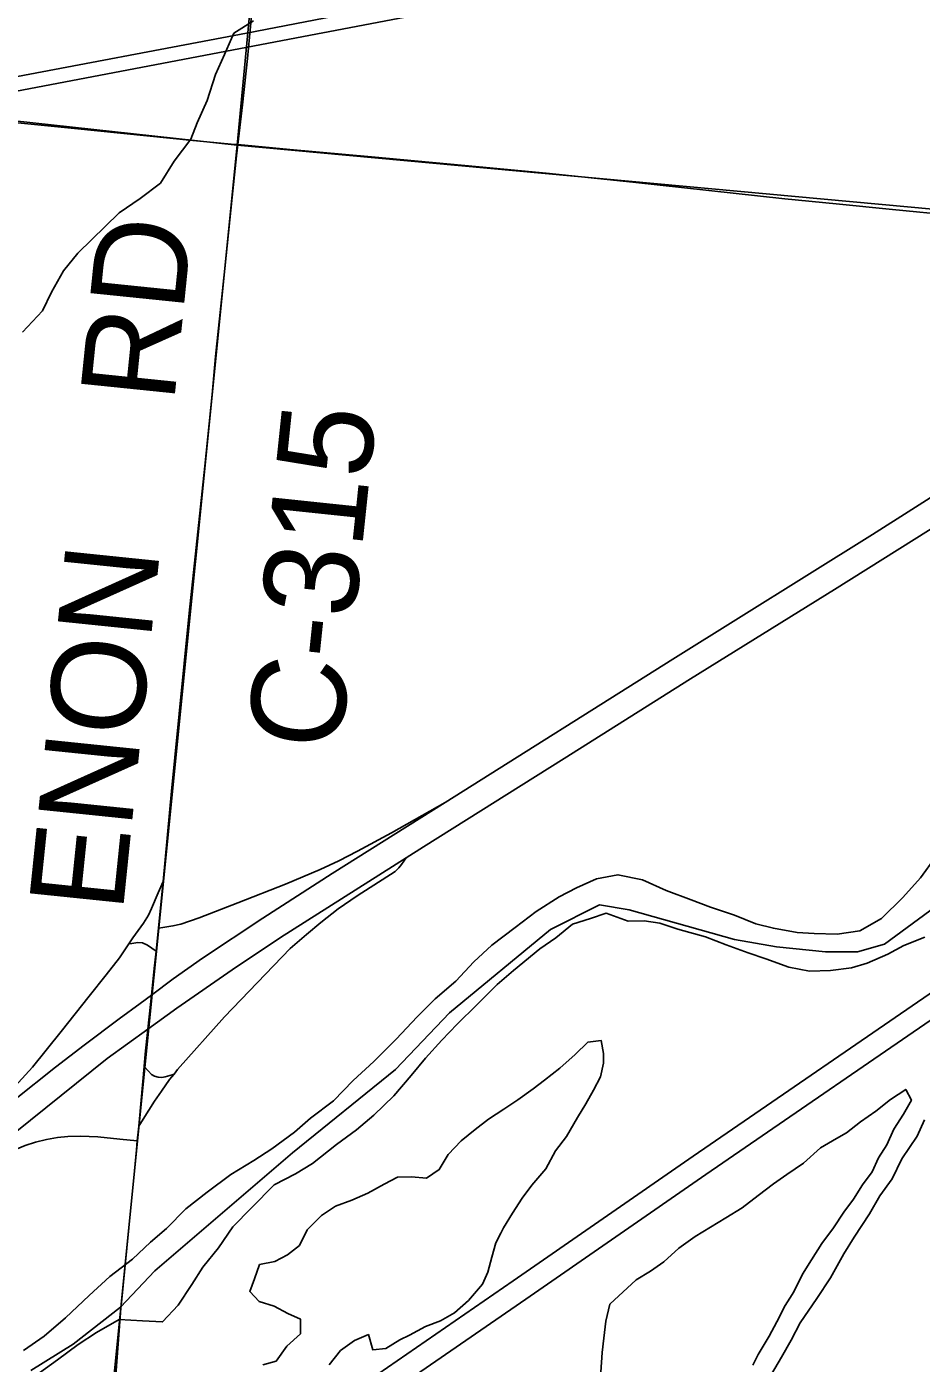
# Model space of a CAD drawing. Extents: x 0 to 34, y 0 to 22.
# Drawn here: x 2.851 to 3.39, y 15.759 to 16.564 of the extents above; entities that cross this region are included whole.
import ezdxf

# ---------------------------------------------------------------- set-up
doc = ezdxf.new("R2010")
doc.units = 0
for name, color, linetype in [('Default', 7, 'Continuous'), ('GM_X_City_Street', 7, 'Continuous'), ('GM_X_County_Road', 7, 'Continuous'), ('GM_X_County_Road_Text', 7, 'Continuous'), ('GM_X_Interchange_Ramps', 7, 'Continuous'), ('GM_X_Major_River', 7, 'Continuous'), ('GM_X_Minor_Lake', 7, 'Continuous'), ('GM_X_Minor_River', 7, 'Continuous'), ('GM_X_Rail_Line', 7, 'Continuous'), ('GM_X_Section', 7, 'Continuous'), ('GM_X_State_Route', 7, 'Continuous')]:
    doc.layers.add(name, color=color, linetype=linetype)

msp = doc.modelspace()

# ---------------------------------------------------------------- linework, layer by layer
at = {"layer": 'Default'}
for points in [[(2.1, 17.59573), (2.1, 16.58828), (2.97812, 16.49217), (3.07459, 17.51121)], [(2.1, 16.58828), (2.1, 15.58132), (2.87773, 15.48948), (2.97812, 16.49217)]]:
    msp.add_lwpolyline(points, close=True, dxfattribs=at)
at = {"layer": 'GM_X_City_Street'}
for points in [[(3.4019, 16.03619), (3.36789, 16.01106), (3.3516, 16.00661), (3.33238, 16.00662), (3.30277, 16.0096), (3.27745, 16.01401), (3.21402, 16.0318), (3.19625, 16.03478), (3.16667, 16.02001), (3.10601, 15.96974), (3.07345, 15.93573), (3.01133, 15.88546), (2.92847, 15.8145), (2.90781, 15.79254), (2.87924, 15.77038), (2.85389, 15.7544)], [(2.85389, 15.7544), (2.87924, 15.77038), (2.90781, 15.79254), (2.92847, 15.8145), (3.01133, 15.88546), (3.07345, 15.93573), (3.10601, 15.96974), (3.16667, 16.02001), (3.19625, 16.03478), (3.21402, 16.0318), (3.27745, 16.01401), (3.30277, 16.0096), (3.33238, 16.00662), (3.3516, 16.00661), (3.36789, 16.01106), (3.4019, 16.03619)]]:
    msp.add_lwpolyline(points, dxfattribs=at)
at = {"layer": 'GM_X_County_Road'}
msp.add_line((2.91792, 15.89272), (2.91874, 15.90146), dxfattribs=at)
for points in [[(2.97837, 16.49255), (2.98124, 16.51654), (2.98428, 16.54434), (2.986, 16.56374), (2.98874, 16.59379), (2.99255, 16.63087), (2.99634, 16.66794), (2.99894, 16.69376), (3.00125, 16.7176), (3.00368, 16.7471), (3.00661, 16.77881), (3.00876, 16.80356), (3.01273, 16.84371), (3.02155, 16.93329), (3.03145, 17.03525), (3.04182, 17.14033), (3.04653, 17.18666), (3.0502, 17.22374), (3.05249, 17.24848), (3.05784, 17.30412), (3.06286, 17.35669), (3.06386, 17.36665)], [(2.1, 16.53048), (2.1009, 16.5306), (2.1287, 16.53392), (2.18123, 16.53969), (2.26467, 16.54874), (2.31107, 16.55357), (2.3266, 16.5548), (2.33595, 16.55516), (2.34533, 16.55503), (2.35778, 16.55419), (2.41922, 16.54792), (2.47798, 16.54185), (2.52745, 16.53676), (2.6698, 16.52317), (2.7348, 16.51697), (2.7657, 16.51363), (2.80591, 16.50961), (2.88015, 16.50226), (2.95129, 16.4951), (2.9767, 16.4927), (2.97837, 16.49255)], [(2.94316, 16.14982), (2.94923, 16.21034), (2.95855, 16.29886), (2.96298, 16.34216), (2.96509, 16.36491), (2.96671, 16.38197), (2.97065, 16.41795), (2.97495, 16.46098), (2.97755, 16.48571), (2.97837, 16.49255)], [(2.97837, 16.49255), (3.00975, 16.48956), (3.05897, 16.48522), (3.12374, 16.47912), (3.16403, 16.47542), (3.21637, 16.47004), (3.30781, 16.45986), (3.33874, 16.4569), (3.37274, 16.45355), (3.40986, 16.44998)], [(2.93344, 16.04896), (2.93841, 16.10325), (2.94256, 16.14387), (2.94316, 16.14982)], [(2.92922, 16.00702), (2.93067, 16.02084), (2.93215, 16.03496), (2.93344, 16.04896)], [(2.92202, 15.93755), (2.92266, 15.94484), (2.92425, 15.95988), (2.92642, 15.9804), (2.92811, 15.99646), (2.92922, 16.00702)], [(2.91874, 15.90146), (2.92023, 15.91716), (2.92202, 15.93755)], [(2.91617, 15.87463), (2.91741, 15.88735), (2.91792, 15.89272)], [(2.89704, 15.66935), (2.89755, 15.67486), (2.89763, 15.6757), (2.90075, 15.70615), (2.90467, 15.74642), (2.9075, 15.78663), (2.90804, 15.79201), (2.90817, 15.79337), (2.91286, 15.84038), (2.91617, 15.87463)]]:
    msp.add_lwpolyline(points, dxfattribs=at)
at = {"layer": 'GM_X_Interchange_Ramps'}
for points in [[(3.10321, 16.09644), (3.07101, 16.07812), (3.05044, 16.06714), (3.03932, 16.06132), (3.02794, 16.05605), (3.00714, 16.04731), (2.97852, 16.036), (2.95512, 16.02696), (2.94403, 16.02321), (2.93935, 16.02214), (2.93333, 16.02124), (2.93067, 16.02084)], [(2.91874, 15.90146), (2.92145, 15.90572), (2.92834, 15.91655), (2.93252, 15.92268), (2.93735, 15.92956), (2.94002, 15.93292), (2.94222, 15.93569), (2.97043, 15.96737), (3.01004, 16.00849), (3.01973, 16.01699), (3.02853, 16.02413), (3.03879, 16.03244), (3.05038, 16.04027), (3.07328, 16.05498), (3.07543, 16.05717), (3.07696, 16.05913), (3.07979, 16.06315)], [(2.93344, 16.04896), (2.93049, 16.04199), (2.92653, 16.03263), (2.92459, 16.02861), (2.92164, 16.02379), (2.91524, 16.01502), (2.91279, 16.01132), (2.90718, 16.00286), (2.89919, 15.99274), (2.88888, 15.97986), (2.8721, 15.95854), (2.85476, 15.93703), (2.84644, 15.92785), (2.83565, 15.91674), (2.82413, 15.9054), (2.79041, 15.87142)], [(2.92922, 16.00702), (2.92675, 16.00876), (2.92409, 16.01063), (2.921, 16.01188), (2.91826, 16.01207), (2.9146, 16.01156), (2.91279, 16.01132)], [(2.92202, 15.93755), (2.92465, 15.93476), (2.92652, 15.93276), (2.92834, 15.93162), (2.93052, 15.93107), (2.93259, 15.93087), (2.93466, 15.93119), (2.93891, 15.93256), (2.94002, 15.93292)], [(2.80194, 15.86078), (2.82531, 15.87675), (2.83515, 15.88277), (2.84325, 15.88694), (2.85031, 15.88983), (2.85656, 15.89191), (2.86327, 15.89353), (2.86987, 15.89469), (2.876, 15.89538), (2.88375, 15.89562), (2.89417, 15.89504), (2.90736, 15.89376), (2.91792, 15.89272)]]:
    msp.add_lwpolyline(points, dxfattribs=at)
at = {"layer": 'GM_X_Major_River'}
for points in [[(3.39849, 16.06348), (3.38947, 16.05113), (3.37893, 16.03919), (3.36609, 16.02654), (3.353, 16.01923), (3.33926, 16.01725), (3.32557, 16.01756), (3.31532, 16.01817), (3.30092, 16.02077), (3.29033, 16.02329), (3.27752, 16.02852), (3.26317, 16.0334), (3.25148, 16.03785), (3.2364, 16.04351), (3.22209, 16.04991), (3.20733, 16.05291), (3.19434, 16.05053), (3.18243, 16.0451), (3.17204, 16.03962), (3.15814, 16.03081), (3.14538, 16.0212), (3.13144, 16.01049), (3.12057, 16.00046), (3.10966, 15.98892), (3.09724, 15.97816), (3.08635, 15.96738), (3.07388, 15.95397), (3.06026, 15.94058), (3.04784, 15.92907), (3.03615, 15.91678), (3.02222, 15.90645), (3.01252, 15.89792), (2.99898, 15.88795), (2.98818, 15.88097), (2.97429, 15.87253), (2.95998, 15.86182), (2.9472, 15.85184), (2.93552, 15.83994), (2.92583, 15.83179), (2.91495, 15.82138), (2.9014, 15.81104), (2.88897, 15.79953), (2.8746, 15.78616), (2.8618, 15.77504), (2.84943, 15.76657)], [(3.39208, 16.01532), (3.37942, 16.01027), (3.36979, 16.00516), (3.3575, 15.99973), (3.34793, 15.9969), (3.33534, 15.99528), (3.32278, 15.9948), (3.31029, 15.99736), (3.29632, 16.00224), (3.28576, 16.00589), (3.27255, 16.01075), (3.26011, 16.0156), (3.24348, 16.02015), (3.23253, 16.02382), (3.22305, 16.02517), (3.21354, 16.025), (3.20034, 16.02986), (3.19076, 16.02665), (3.18003, 16.02309), (3.16996, 16.01495), (3.1603, 16.00832), (3.14441, 15.99536), (3.13471, 15.98683), (3.12227, 15.97456), (3.1106, 15.96303), (3.10125, 15.95335), (3.0915, 15.94254), (3.08289, 15.93209), (3.07235, 15.91977), (3.0603, 15.90825), (3.04983, 15.89936), (3.03784, 15.8905), (3.02351, 15.87903), (3.01309, 15.8728), (3.0004, 15.86624), (2.98677, 15.85247), (2.97548, 15.84094), (2.96683, 15.8282), (2.95744, 15.81662), (2.95074, 15.80613), (2.94247, 15.79376), (2.93312, 15.7837), (2.92096, 15.78436)], [(2.92096, 15.78436), (2.9069, 15.78505), (2.89342, 15.77737), (2.88222, 15.77002), (2.86984, 15.76079), (2.85902, 15.75304)]]:
    msp.add_lwpolyline(points, dxfattribs=at)
at = {"layer": 'GM_X_Minor_Lake'}
for points in [[(3.13674, 15.83708), (3.13845, 15.8404), (3.14388, 15.84907), (3.14969, 15.85811), (3.15548, 15.86601), (3.16396, 15.87578), (3.16979, 15.88672), (3.17636, 15.89537), (3.18296, 15.90668), (3.188, 15.91497), (3.19266, 15.92327), (3.19693, 15.93119), (3.19856, 15.93952), (3.19862, 15.94522), (3.1972, 15.95321), (3.18922, 15.95217), (3.18152, 15.94467), (3.17231, 15.93643), (3.1631, 15.92932), (3.1562, 15.92409), (3.147, 15.91737), (3.13857, 15.91178), (3.12938, 15.90582), (3.12133, 15.89946), (3.11289, 15.89273), (3.10519, 15.88447), (3.09976, 15.87543), (3.09209, 15.87021), (3.08299, 15.87108), (3.07463, 15.8708), (3.0666, 15.86672), (3.05666, 15.86115), (3.04711, 15.85709), (3.03719, 15.85342), (3.02876, 15.84782), (3.0203, 15.83919), (3.01562, 15.82976), (3.00834, 15.82415), (3.00069, 15.82007), (2.99155, 15.81829)], [(3.31219, 15.80012), (3.31349, 15.80219), (3.31855, 15.81238), (3.32397, 15.82105), (3.33017, 15.83084), (3.33712, 15.84025), (3.34332, 15.84967), (3.34911, 15.85757), (3.35454, 15.86624), (3.36034, 15.87414), (3.36423, 15.88245), (3.36927, 15.89036), (3.37357, 15.8998), (3.37937, 15.90884), (3.38404, 15.91714), (3.3807, 15.92364), (3.37151, 15.91767), (3.36268, 15.91057), (3.35349, 15.90422), (3.34505, 15.89749), (3.33893, 15.89415), (3.32936, 15.88857), (3.31899, 15.8792), (3.30903, 15.87249), (3.30098, 15.86689), (3.29178, 15.85979), (3.28219, 15.85231), (3.27224, 15.84636), (3.25387, 15.83519), (3.24391, 15.8281), (3.23507, 15.81985), (3.22702, 15.81425), (3.21822, 15.80905), (3.20247, 15.79443)], [(3.03335, 15.75778), (3.04029, 15.76643), (3.04873, 15.7724), (3.05713, 15.77609), (3.05967, 15.76695), (3.06766, 15.76761), (3.07608, 15.77282), (3.08181, 15.77579), (3.09138, 15.78099), (3.10054, 15.78429), (3.10895, 15.78912), (3.1174, 15.79661), (3.12588, 15.80638), (3.12901, 15.81356), (3.1314, 15.82264), (3.13378, 15.83134), (3.13674, 15.83708)], [(2.99155, 15.81829), (2.9884, 15.80959), (2.98565, 15.80203), (2.99127, 15.79589), (3.00035, 15.79312), (3.00866, 15.78884), (3.01621, 15.78533), (3.01611, 15.7766), (3.00804, 15.76911), (3.00147, 15.76007), (2.99346, 15.75789)], [(3.28862, 15.75769), (3.29174, 15.76411), (3.29834, 15.77504), (3.303, 15.78371), (3.30806, 15.79352), (3.31219, 15.80012)], [(3.20247, 15.79443), (3.20006, 15.78421), (3.1988, 15.77397), (3.19793, 15.76525), (3.19702, 15.75349)]]:
    msp.add_lwpolyline(points, dxfattribs=at)
at = {"layer": 'GM_X_Minor_River'}
for points in [[(2.84879, 16.37971), (2.86073, 16.39247), (2.86619, 16.40379), (2.87356, 16.41661), (2.88205, 16.42714), (2.90704, 16.45151), (2.91969, 16.46009), (2.93196, 16.46943), (2.9401, 16.48262), (2.95014, 16.49579), (2.95406, 16.50561), (2.95992, 16.51921), (2.96505, 16.53472), (2.97052, 16.5468), (2.976, 16.55964), (2.98787, 16.56709)], [(3.29724, 15.74771), (3.30578, 15.76242), (3.3116, 15.7726), (3.31705, 15.78316), (3.32711, 15.79785), (3.33524, 15.81028), (3.34339, 15.82461), (3.34959, 15.83479), (3.35888, 15.84872), (3.3651, 15.85966), (3.37244, 15.86982), (3.37829, 15.8819), (3.38757, 15.89545), (3.39187, 15.90528)]]:
    msp.add_lwpolyline(points, dxfattribs=at)
at = {"layer": 'GM_X_Rail_Line'}
for points in [[(4.0546, 16.76124), (3.96165, 16.74674), (3.46773, 16.65335), (2.98371, 16.5597), (2.52515, 16.47289), (2.19649, 16.40606), (2.1, 16.38706)], [(2.1, 16.38195), (2.15252, 16.39291), (3.47019, 16.64396), (4.05688, 16.74658), (4.11037, 16.75743)], [(2.932, 15.64588), (3.07065, 15.74137), (3.15191, 15.79742), (3.26024, 15.87246), (3.41574, 15.97923), (3.54897, 16.07079), (3.83938, 16.27039), (3.91067, 16.31508), (3.96338, 16.34568), (4.00551, 16.36832), (4.04873, 16.38909), (4.09944, 16.41111), (4.2263, 16.46369), (4.35548, 16.51692), (4.47235, 16.56519), (4.70404, 16.66052)], [(2.932, 15.64588), (2.95977, 15.66766), (2.97762, 15.68238), (3.02042, 15.71945), (3.04883, 15.7418), (3.06285, 15.75219), (3.14429, 15.80836), (3.25263, 15.88341), (3.40815, 15.99019), (3.54137, 16.08175), (3.83202, 16.2815), (3.90374, 16.32647), (3.95684, 16.3573)]]:
    msp.add_lwpolyline(points, dxfattribs=at)
at = {"layer": 'GM_X_Section'}
for points in [[(3.07459, 17.51121), (4.09568, 17.40069), (4.00362, 16.39786), (2.97812, 16.49217)], [(2.97812, 16.49217), (4.00362, 16.39786), (3.88999, 15.39575), (2.87773, 15.48948)]]:
    msp.add_lwpolyline(points, close=True, dxfattribs=at)
at = {"layer": 'GM_X_State_Route'}
for points in [[(3.07979, 16.06315), (3.09022, 16.06979), (3.17486, 16.12302), (3.25101, 16.1708), (3.33771, 16.22464), (3.41483, 16.27311), (3.50248, 16.32849), (3.59185, 16.38465), (3.68214, 16.44182), (3.74381, 16.48042), (3.826, 16.53265), (3.91643, 16.58959), (4.01411, 16.65123), (4.10427, 16.70808), (4.19935, 16.76776), (4.28566, 16.82246), (4.33945, 16.85614)], [(2.79041, 15.87142), (2.82127, 15.89847), (2.84397, 15.91741), (2.86874, 15.93709), (2.88592, 15.95027), (2.90705, 15.9662), (2.9197, 15.97532), (2.92642, 15.9804), (2.9395, 15.9903), (2.95727, 16.00278), (2.99347, 16.02686), (3.03531, 16.05366), (3.10321, 16.09644), (3.24033, 16.18282), (3.36055, 16.25774), (3.50059, 16.34667), (3.54787, 16.37651), (3.6635, 16.44942), (3.85019, 16.56687), (3.90801, 16.60331), (3.96315, 16.63815)], [(2.80194, 15.86078), (2.80794, 15.86648), (2.84445, 15.89772), (2.89985, 15.94228), (2.92425, 15.95988), (2.94177, 15.97253), (2.97498, 15.99571), (3.00422, 16.01506), (3.07979, 16.06315)]]:
    msp.add_lwpolyline(points, dxfattribs=at)

# ---------------------------------------------------------------- texts
at = {"layer": 'GM_X_County_Road_Text'}
for s, rotation, p in [('RD', 84.14318, (2.93998, 16.33655)), ('C-315', 84.00176, (3.0404, 16.12672)), ('ENON', 84.11859, (2.90911, 16.02971))]:
    msp.add_text(s, height=0.056818, rotation=rotation, dxfattribs=at).set_placement(p)

doc.saveas('drawing.dxf')
